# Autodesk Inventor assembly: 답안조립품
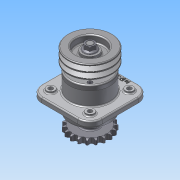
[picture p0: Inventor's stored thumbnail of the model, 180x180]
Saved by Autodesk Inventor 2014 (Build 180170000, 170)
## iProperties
Created: 2015-09
Part Number: 답안조립품
Document SubType Name: Assembly
Designer: study
Author: study
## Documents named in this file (11)
- C:\Users\study\Desktop\450909V1005\답안조립품.iam
- C:\Users\study\Desktop\450909V1005\1-본체.ipt
- C:\Users\study\Desktop\450909V1005\6-베어링 6206.ipt
- C:\Users\study\Desktop\450909V1005\2-커버.ipt
- C:\Users\study\Desktop\450909V1005\8-오일실 30x42.ipt
- C:\Users\study\Desktop\450909V1005\3-축.ipt
- C:\Users\study\Desktop\450909V1005\11-키 6x6.ipt
- C:\Users\study\Desktop\450909V1005\4-V벨트풀리.ipt
- C:\Users\study\Desktop\450909V1005\5-체인 스프로킷.ipt
- C:\Users\study\Desktop\450909V1005\9-M16-너트.ipt
- C:\Users\study\Desktop\450909V1005\10-M6.ipt
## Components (22 placed, 10 different names)
1. 1-본체:1
2. 6-베어링 6206:1
3. 6-베어링 6206:2
4. 2-커버:1
5. 2-커버:2
6. 8-8-오일실 30x42:1
7. 8-8-오일실 30x42:2
8. 3-축:1 — 각도:1, 각도:2, 각도:5, 각도:6
9. 11-키 6x6:1 — 각도:1, 각도:3
10. 11-키 6x6:2 — 각도:2, 각도:4
11. 4-V벨트풀리:1 — 각도:3
12. 5-체인 스프로킷:1 — 각도:4
13. 9-M16 너트:1 — 각도:6
14. 9-M16 너트:2 — 각도:5
15. 10-M6:1
16. 10-M6:3
17. 10-M6:4
18. 10-M6:5
19. 10-M6:2
20. 10-M6:6
21. 10-M6:7
22. 10-M6:8
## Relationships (6: Angle 6)
- 각도:1 [Angle]: 3-축:1 ↔ 11-키 6x6:1
- 각도:2 [Angle]: 3-축:1 ↔ 11-키 6x6:2
- 각도:3 [Angle]: 11-키 6x6:1 ↔ 4-V벨트풀리:1
- 각도:4 [Angle]: 11-키 6x6:2 ↔ 5-체인 스프로킷:1
- 각도:5 [Angle]: 3-축:1 ↔ 9-M16 너트:2
- 각도:6 [Angle]: 3-축:1 ↔ 9-M16 너트:1
